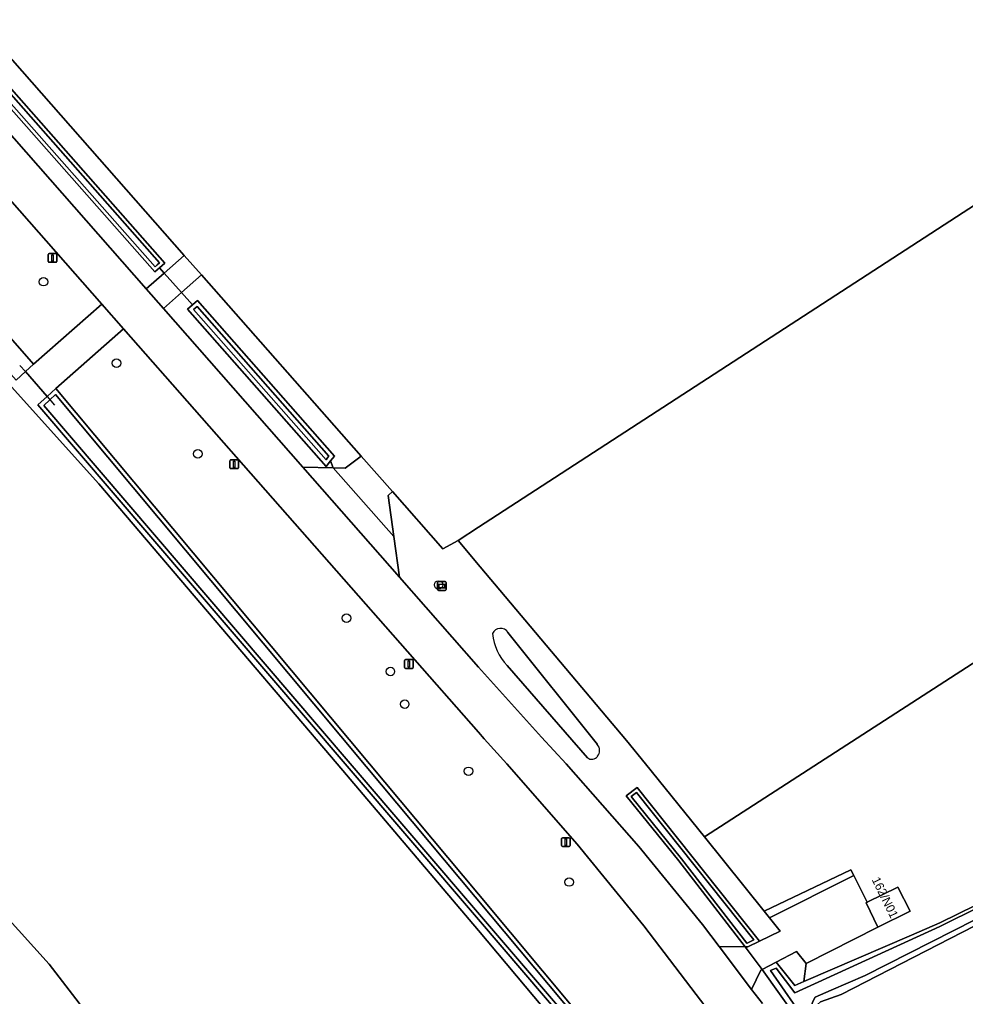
# Model space of a CAD drawing. Extents: x 156061 to 157804, y 383437 to 385640.
# Drawn here: x 157447.3 to 157555.9, y 383973.3 to 384085.5 of the extents above; entities that cross this region are included whole.
import ezdxf

# ---------------------------------------------------------------- set-up
doc = ezdxf.new("R2010")
doc.units = 0
for name, color, linetype in [('IMGEO_Berm_groen', 7, 'Continuous'), ('IMGEO_Boom', 7, 'Continuous'), ('IMGEO_Duiker', 7, 'Continuous'), ('IMGEO_Grasland_overig', 7, 'Continuous'), ('IMGEO_Groenvoorziening', 7, 'Continuous'), ('IMGEO_Haag', 7, 'Continuous'), ('IMGEO_Hek', 7, 'Continuous'), ('IMGEO_Lichtmast', 7, 'Continuous'), ('IMGEO_Naaldbos', 7, 'Continuous'), ('IMGEO_Oever', 7, 'Continuous'), ('IMGEO_Pand', 7, 'Continuous'), ('IMGEO_Pand_nummerreeks', 7, 'Continuous'), ('IMGEO_Rijbaan_lokaal_gesloten', 7, 'Continuous'), ('IMGEO_Rijbaan_lokaal_open', 7, 'Continuous'), ('IMGEO_Verklikker', 7, 'Continuous'), ('IMGEO_Waterloop', 7, 'Continuous')]:
    doc.layers.add(name, color=color, linetype=linetype)

msp = doc.modelspace()

# ---------------------------------------------------------------- linework, layer by layer
at = {"layer": 'IMGEO_Berm_groen'}
for points in [[(157340.41, 384192.86), (157351.29, 384180.48), (157461.84, 384054.56), (157463.91, 384056.38), (157463.38, 384056.98), (157462.83, 384056.5), (157343.68, 384191.47)], [(157318.6, 384190.2), (157317.96, 384189.64), (157344.19, 384159.18), (157364.55, 384136), (157393.61, 384102.92), (157399.11, 384096.66), (157446.05, 384043.69), (157456.41, 384032.18), (157483.79, 384000), (157500, 383980.87), (157519.27, 383957.9), (157520.38, 383958.3), (157500, 383982.12), (157484.69, 384000), (157449.42, 384041.22), (157450.46, 384042.19), (157447.97, 384045.05), (157446.91, 384044.08), (157389.32, 384108.91), (157390.82, 384110.23), (157391.84, 384111.13), (157448.89, 384045.9), (157456.76, 384052.82), (157342.96, 384182.28)], [(157527.33, 383970.45), (157519, 383981.4), (157511.33, 383990.78), (157503.27, 384000), (157500.68, 384002.86), (157500, 384003.63), (157459.26, 384049.98), (157451.47, 384043.13), (157487.5, 384000), (157500, 383985.04), (157521.88, 383958.85)], [(157503.4, 384015.1), (157513.66, 384002.23)], [(157512.54, 384000.71), (157503.29, 384011.29)]]:
    msp.add_lwpolyline(points, dxfattribs=at)
for points in [[(157463.91, 384056.38), (157461.84, 384054.56), (157463.82, 384052.3), (157465.9, 384054.13)], [(157466.6, 384052.22), (157467.16, 384052.71), (157465.9, 384054.13), (157463.82, 384052.3), (157479.83, 384034.07), (157483.33, 384033.99), (157483.03, 384034.79), (157482.52, 384034.17)], [(157483.33, 384033.99), (157479.83, 384034.07), (157490.93, 384021.43), (157490.28, 384026.1)], [(157500.2, 384022.65), (157497.66, 384025.67), (157495.9, 384024.71), (157490.12, 384031.28), (157489.62, 384030.82), (157490.28, 384026.1), (157490.93, 384021.43), (157500, 384011.09), (157507.25, 384003.05), (157510.09, 384000), (157518.43, 383990.52), (157525.74, 383981.55), (157527.64, 383979.04), (157530.64, 383978.98), (157523.02, 383988.86), (157516.98, 383996.33), (157518.23, 383997.3), (157532.29, 383979.64), (157534.64, 383980.79), (157533.45, 383982.31), (157532.83, 383983.08), (157525.95, 383991.61), (157519.18, 384000), (157517.01, 384002.7)]]:
    msp.add_lwpolyline(points, close=True, dxfattribs=at)
for centre, radius, start, end in [((157502.55, 384014.57), 1, 31.6822, 156.9523), ((157507.72, 384015.51), 6.11, 185.0653, 223.6347), ((157512.91, 384001.54), 1.01, 318.1974, 42.3929), ((157513.03, 384001.28), 0.758, 229.1685, 326.9357)]:
    msp.add_arc(centre, radius, start, end, dxfattribs=at)
at = {"layer": 'IMGEO_Boom'}
for centre in [(157450.06, 384055.38), (157458.43, 384046.03), (157467.78, 384035.61), (157495.43, 384020.55), (157484.85, 384016.73), (157489.89, 384010.6), (157491.54, 384006.85), (157498.86, 383999.15), (157510.42, 383986.43)]:
    msp.add_circle(centre, 0.489, dxfattribs=at)
at = {"layer": 'IMGEO_Duiker'}
msp.add_lwpolyline([(157447.34, 384045.77), (157447.97, 384045.05), (157450.46, 384042.19), (157451.33, 384041.19)], dxfattribs=at)
at = {"layer": 'IMGEO_Grasland_overig'}
for points in [[(157468.2, 384056.16), (157466.22, 384058.41), (157463.91, 384056.38), (157465.9, 384054.13)], [(157451.47, 384043.13), (157459.26, 384049.98), (157456.76, 384052.82), (157448.89, 384045.9), (157447.97, 384045.05), (157450.46, 384042.19)], [(157489.62, 384030.82), (157490.12, 384031.28), (157486.53, 384035.35), (157484.7, 384033.96), (157483.33, 384033.99), (157490.28, 384026.1)]]:
    msp.add_lwpolyline(points, close=True, dxfattribs=at)
at = {"layer": 'IMGEO_Groenvoorziening'}
for points in [[(157375.38, 384222.59), (157376.59, 384220.76), (157342.51, 384199.14), (157412.58, 384119.43), (157466.22, 384058.41), (157468.2, 384056.16), (157486.53, 384035.35), (157490.12, 384031.28), (157495.9, 384024.71), (157497.66, 384025.67), (157500, 384027.19), (157642, 384119.41), (157643.26, 384117.4), (157752.8, 384188.65), (157752.54, 384194.33), (157751.65, 384205.4), (157750.08, 384220.37), (157749.32, 384226.2), (157748.06, 384232.65), (157745.14, 384247.49), (157743.64, 384254.59), (157738.42, 384274.55), (157728.47, 384313.42)], [(157340.2, 384197.97), (157344.9, 384192.66), (157463.98, 384057.5), (157463.38, 384056.98), (157463.91, 384056.38), (157466.22, 384058.41), (157412.58, 384119.43), (157342.51, 384199.14), (157376.59, 384220.76), (157375.38, 384222.59), (157343.39, 384202.41)], [(157642, 384119.41), (157500, 384027.19), (157497.66, 384025.67), (157500.2, 384022.65), (157517.01, 384002.7), (157519.18, 384000), (157525.95, 383991.61), (157642.66, 384067.03), (157664.05, 384080.85), (157668.86, 384071.41), (157701.95, 384072.77), (157719.58, 384083.63), (157721.28, 384082.41), (157730.2, 384064.28), (157731.75, 384064.23), (157756.47, 384074.37), (157756.55, 384074.87), (157757.36, 384079.82), (157760.48, 384099.13)], [(157319.02, 384000), (157343.68, 383972.81), (157358.66, 383956.01), (157373.77, 383939.34), (157386.41, 383926.07), (157399.25, 383913.04), (157423.1, 383919.46), (157447.61, 383928.82), (157500, 383950.08), (157519.27, 383957.9), (157500, 383980.87), (157483.79, 384000), (157456.41, 384032.18), (157446.05, 384043.69), (157399.11, 384096.66)], [(157683.71, 383998.2), (157679.87, 383996.94), (157678.86, 384000), (157676.51, 384007.11), (157673.93, 384007.49), (157671.91, 384009.46), (157668.41, 384017.54), (157659.62, 384031.98), (157656.19, 384033.53), (157656.8, 384032.66), (157593.24, 384000), (157541.68, 383973.51), (157539.29, 383972.68), (157538.96, 383972.37), (157554.47, 383951.89), (157556.32, 383951.02)], [(157427.78, 384002.36), (157450.71, 383977), (157457.73, 383967.9)], [(157542, 383963.16), (157538.56, 383967.99), (157532.58, 383976.37), (157532.42, 383976.29), (157531.38, 383974.1), (157532.61, 383972.47)]]:
    msp.add_lwpolyline(points, dxfattribs=at)
for points in [[(157656.19, 384033.53), (157659.62, 384031.98), (157642.66, 384067.03), (157525.95, 383991.61), (157532.83, 383983.08), (157542.78, 383987.84), (157543.11, 383987.19), (157544.65, 383984.1), (157548.18, 383985.84), (157549.57, 383983.08), (157545.89, 383981.26), (157537.64, 383977.09), (157537.39, 383975.02), (157549.75, 383980.34), (157553.01, 383981.76), (157590.21, 384000)], [(157467.16, 384052.71), (157467.74, 384053.23), (157483.49, 384035.34), (157483.03, 384034.79), (157483.33, 384033.99), (157484.7, 384033.96), (157486.53, 384035.35), (157468.2, 384056.16), (157465.9, 384054.13)], [(157533.45, 383982.31), (157543.11, 383987.19), (157542.78, 383987.84), (157532.83, 383983.08)], [(157537.39, 383975.02), (157537.64, 383977.09), (157536.53, 383978.45), (157534.2, 383977.23), (157536.33, 383974.56)]]:
    msp.add_lwpolyline(points, close=True, dxfattribs=at)
at = {"layer": 'IMGEO_Haag'}
msp.add_lwpolyline([(157533.45, 383982.31), (157543.11, 383987.19), (157542.78, 383987.84), (157532.83, 383983.08)], close=True, dxfattribs=at)
at = {"layer": 'IMGEO_Hek'}
for points in [[(157376.59, 384220.76), (157342.51, 384199.14), (157412.58, 384119.43), (157466.22, 384058.41)], [(157500, 384027.19), (157642, 384119.41)], [(157466.22, 384058.41), (157468.2, 384056.16)], [(157468.2, 384056.16), (157486.53, 384035.35)], [(157486.53, 384035.35), (157490.12, 384031.28)], [(157490.12, 384031.28), (157495.9, 384024.71)], [(157497.66, 384025.67), (157500, 384027.19)], [(157495.9, 384024.71), (157497.66, 384025.67)], [(157500.2, 384022.65), (157497.66, 384025.67)], [(157519.18, 384000), (157517.01, 384002.7), (157500.2, 384022.65)], [(157525.95, 383991.61), (157519.18, 384000)], [(157532.83, 383983.08), (157525.95, 383991.61)], [(157543.11, 383987.19), (157542.78, 383987.84), (157532.83, 383983.08)], [(157544.65, 383984.1), (157543.11, 383987.19)], [(157545.89, 383981.26), (157537.64, 383977.09)]]:
    msp.add_lwpolyline(points, dxfattribs=at)
at = {"layer": 'IMGEO_Lichtmast'}
for p, q in [((157450.59, 384057.71), (157450.59, 384058.51)), ((157450.59, 384058.51), (157450.59, 384057.71)), ((157450.69, 384058.61), (157451.48, 384058.61)), ((157451.48, 384058.61), (157450.69, 384058.61)), ((157451.58, 384058.51), (157451.58, 384057.71)), ((157451.58, 384057.71), (157451.58, 384058.51)), ((157451.48, 384057.61), (157450.69, 384057.61)), ((157450.69, 384057.61), (157451.48, 384057.61)), ((157471.45, 384034.01), (157471.45, 384034.81)), ((157471.45, 384034.81), (157471.45, 384034.01)), ((157471.55, 384034.91), (157472.34, 384034.91)), ((157472.34, 384034.91), (157471.55, 384034.91)), ((157472.44, 384034.81), (157472.44, 384034.01)), ((157472.44, 384034.01), (157472.44, 384034.81)), ((157472.34, 384033.91), (157471.55, 384033.91)), ((157471.55, 384033.91), (157472.34, 384033.91)), ((157491.53, 384011.07), (157491.53, 384011.87)), ((157491.53, 384011.87), (157491.53, 384011.07)), ((157491.63, 384011.97), (157492.42, 384011.97)), ((157492.42, 384011.97), (157491.63, 384011.97)), ((157492.52, 384011.87), (157492.52, 384011.07)), ((157492.52, 384011.07), (157492.52, 384011.87)), ((157492.42, 384010.97), (157491.63, 384010.97)), ((157491.63, 384010.97), (157492.42, 384010.97)), ((157509.55, 383990.61), (157509.55, 383991.41)), ((157509.55, 383991.41), (157509.55, 383990.61)), ((157509.65, 383991.51), (157510.44, 383991.51)), ((157510.44, 383991.51), (157509.65, 383991.51)), ((157510.54, 383991.41), (157510.54, 383990.61)), ((157510.54, 383990.61), (157510.54, 383991.41)), ((157510.44, 383990.51), (157509.65, 383990.51)), ((157509.65, 383990.51), (157510.44, 383990.51))]:
    msp.add_line(p, q, dxfattribs=at)
for points in [[(157451.01, 384058.48), (157451.16, 384058.48), (157451.16, 384057.73), (157451.01, 384057.73), (157451.01, 384058.48)], [(157471.87, 384034.78), (157472.02, 384034.78), (157472.02, 384034.03), (157471.87, 384034.03), (157471.87, 384034.78)], [(157491.95, 384011.85), (157492.1, 384011.85), (157492.1, 384011.1), (157491.95, 384011.1), (157491.95, 384011.85)], [(157509.97, 383991.38), (157510.12, 383991.38), (157510.12, 383990.63), (157509.97, 383990.63), (157509.97, 383991.38)]]:
    msp.add_lwpolyline(points, dxfattribs=at)
for centre, start, end in [((157450.69, 384058.51), 90, 180), ((157450.69, 384058.51), 90, 180), ((157451.48, 384058.51), 0, 90), ((157451.48, 384058.51), 360, 90), ((157450.69, 384057.71), 180, 270), ((157450.69, 384057.71), 180, 270), ((157451.48, 384057.71), 270, 0), ((157451.48, 384057.71), 270, 0), ((157471.55, 384034.81), 90, 180), ((157471.55, 384034.81), 90, 180), ((157472.34, 384034.81), 0, 90), ((157472.34, 384034.81), 360, 90), ((157471.55, 384034.01), 180, 270), ((157471.55, 384034.01), 180, 270), ((157472.34, 384034.01), 270, 0), ((157472.34, 384034.01), 270, 0), ((157491.63, 384011.87), 90, 180), ((157491.63, 384011.87), 90, 180), ((157492.42, 384011.87), 0, 90), ((157492.42, 384011.87), 360, 90), ((157491.63, 384011.07), 180, 270), ((157491.63, 384011.07), 180, 270), ((157492.42, 384011.07), 270, 0), ((157492.42, 384011.07), 270, 0), ((157509.65, 383991.41), 90, 180), ((157509.65, 383991.41), 90, 180), ((157510.44, 383991.41), 0, 90), ((157510.44, 383991.41), 360, 90), ((157509.65, 383990.61), 180, 270), ((157509.65, 383990.61), 180, 270), ((157510.44, 383990.61), 270, 0), ((157510.44, 383990.61), 270, 0)]:
    msp.add_arc(centre, 0.1, start, end, dxfattribs=at)
at = {"layer": 'IMGEO_Naaldbos'}
msp.add_lwpolyline([(157427.78, 384002.36), (157428.16, 383997.33), (157425.96, 383992.38), (157421.54, 383990.17), (157416.03, 383990.5), (157424.72, 383980.52), (157429.47, 383965.92), (157425.19, 383960), (157425.98, 383955.9), (157432.13, 383957.26), (157438.21, 383958.78), (157446.36, 383961.6), (157453.38, 383965.1), (157457.73, 383967.9), (157450.71, 383977)], close=True, dxfattribs=at)
at = {"layer": 'IMGEO_Oever'}
for points in [[(157343.68, 384191.47), (157462.83, 384056.5), (157463.38, 384056.98), (157463.98, 384057.5), (157344.9, 384192.66)], [(157344.59, 384192.37), (157463.38, 384057.54), (157463.1, 384057.3), (157462.87, 384057.1), (157385.2, 384145.03), (157343.99, 384191.76)], [(157500, 383985.04), (157487.5, 384000), (157451.47, 384043.13), (157450.46, 384042.19), (157449.42, 384041.22), (157484.69, 384000), (157500, 383982.12), (157520.38, 383958.3), (157521.18, 383957.37), (157500, 383948.87), (157447.92, 383927.96)], [(157520.75, 383958.62), (157500.37, 383982.43), (157485.06, 384000.31), (157450.08, 384041.18), (157450.78, 384041.83), (157451.42, 384042.43), (157487.13, 383999.69), (157499.63, 383984.73), (157521.74, 383958.27)], [(157538.96, 383972.37), (157539.29, 383972.68), (157541.68, 383973.51), (157593.24, 384000), (157656.8, 384032.66), (157656.19, 384033.53), (157590.21, 384000), (157553.01, 383981.76), (157549.75, 383980.34), (157537.39, 383975.02), (157536.33, 383974.56), (157534.2, 383977.23), (157532.58, 383976.37), (157538.56, 383967.99), (157542, 383963.16)], [(157563.7, 383930.34), (157553.42, 383947.27), (157549.77, 383953.21), (157537.79, 383970.15), (157533.55, 383976.27), (157534.18, 383976.52), (157536.35, 383973.72), (157553, 383981.32), (157590.9, 384000.13)], [(157448.61, 383926.22), (157451.61, 383927.43), (157473.7, 383936.38), (157500, 383947.02), (157516, 383953.5), (157523.94, 383956.8), (157529.6, 383959.15), (157531.35, 383957.26), (157531.69, 383956.9), (157532.22, 383957.33), (157532.95, 383957.92), (157532.92, 383958.91), (157530.15, 383962.42), (157521.88, 383958.85), (157500, 383985.04)], [(157559.58, 383983.38), (157544.42, 383975.69), (157540.51, 383974.02), (157538.66, 383973.21), (157538.39, 383972.7), (157538.13, 383971.94), (157538.33, 383971.09), (157545.65, 383961.38), (157551.34, 383953.49), (157553.33, 383951.7), (157563.27, 383945.93)]]:
    msp.add_lwpolyline(points, dxfattribs=at)
for points in [[(157391.84, 384111.13), (157390.82, 384110.23), (157389.32, 384108.91), (157446.91, 384044.08), (157447.97, 384045.05), (157448.89, 384045.9)], [(157467.74, 384053.23), (157467.16, 384052.71), (157466.6, 384052.22), (157482.52, 384034.17), (157483.03, 384034.79), (157483.49, 384035.34)], [(157467.7, 384052.53), (157482.84, 384035.33), (157482.65, 384035.1), (157482.51, 384034.93), (157467.3, 384052.18), (157467.48, 384052.34)], [(157518.23, 383997.3), (157516.98, 383996.33), (157523.02, 383988.86), (157530.64, 383978.98), (157530.94, 383978.98), (157532.29, 383979.64)], [(157518.16, 383996.73), (157531.65, 383979.78), (157530.85, 383979.39), (157530.84, 383979.39), (157523.34, 383989.11), (157517.56, 383996.26)]]:
    msp.add_lwpolyline(points, close=True, dxfattribs=at)
at = {"layer": 'IMGEO_Pand'}
msp.add_lwpolyline([(157544.65, 383984.1), (157544.52, 383984.04), (157545.89, 383981.26), (157549.57, 383983.08), (157548.18, 383985.84)], close=True, dxfattribs=at)
at = {"layer": 'IMGEO_Rijbaan_lokaal_gesloten'}
for points in [[(157342.96, 384182.28), (157456.76, 384052.82), (157459.26, 384049.98), (157500, 384003.63), (157500.68, 384002.86), (157503.27, 384000), (157511.33, 383990.78), (157519, 383981.4), (157527.33, 383970.45), (157530.5, 383965.93), (157530.89, 383965.44), (157535.32, 383959.69), (157540.42, 383951.06), (157542.83, 383947.51), (157548.36, 383938.61), (157552.88, 383931.4), (157563.85, 383910.77)], [(157461.84, 384054.56), (157351.29, 384180.48)], [(157532.61, 383972.47), (157531.38, 383974.1), (157527.64, 383979.04), (157525.74, 383981.55), (157518.43, 383990.52), (157510.09, 384000), (157507.25, 384003.05), (157500, 384011.09), (157490.93, 384021.43), (157479.83, 384034.07), (157463.82, 384052.3), (157461.84, 384054.56)]]:
    msp.add_lwpolyline(points, dxfattribs=at)
at = {"layer": 'IMGEO_Rijbaan_lokaal_open'}
for points in [[(157532.58, 383976.37), (157534.2, 383977.23), (157536.53, 383978.45), (157537.64, 383977.09), (157545.89, 383981.26), (157544.52, 383984.04), (157544.65, 383984.1), (157543.11, 383987.19), (157533.45, 383982.31), (157534.64, 383980.79), (157532.29, 383979.64), (157530.94, 383978.98), (157530.64, 383978.98)], [(157532.58, 383976.37), (157530.64, 383978.98), (157527.64, 383979.04), (157531.38, 383974.1), (157532.42, 383976.29)]]:
    msp.add_lwpolyline(points, close=True, dxfattribs=at)
at = {"layer": 'IMGEO_Verklikker'}
for p, q in [((157495.3, 384020.03), (157495.3, 384020.83)), ((157495.3, 384020.83), (157495.3, 384020.03)), ((157495.4, 384020.93), (157496.19, 384020.93)), ((157496.19, 384020.93), (157495.4, 384020.93)), ((157496.29, 384020.83), (157496.29, 384020.03)), ((157496.29, 384020.03), (157496.29, 384020.83)), ((157496.19, 384019.93), (157495.4, 384019.93)), ((157495.4, 384019.93), (157496.19, 384019.93))]:
    msp.add_line(p, q, dxfattribs=at)
for points in [[(157495.4, 384020.66), (157496.19, 384020.66), (157496.19, 384020.19), (157495.4, 384020.19), (157495.4, 384020.66)], [(157495.47, 384020.59), (157495.47, 384020.26), (157496.13, 384020.26), (157496.13, 384020.59), (157495.47, 384020.59)]]:
    msp.add_lwpolyline(points, dxfattribs=at)
for centre, start, end in [((157495.4, 384020.83), 90, 180), ((157495.4, 384020.83), 90, 180), ((157496.19, 384020.83), 0, 90), ((157496.19, 384020.83), 360, 90), ((157495.4, 384020.03), 180, 270), ((157495.4, 384020.03), 180, 270), ((157496.19, 384020.03), 270, 0), ((157496.19, 384020.03), 270, 0)]:
    msp.add_arc(centre, 0.1, start, end, dxfattribs=at)
at = {"layer": 'IMGEO_Waterloop'}
for points in [[(157343.99, 384191.76), (157385.2, 384145.03), (157462.87, 384057.1), (157463.1, 384057.3), (157463.38, 384057.54), (157344.59, 384192.37)], [(157521.74, 383958.27), (157499.63, 383984.73), (157487.13, 383999.69), (157451.42, 384042.43), (157450.78, 384041.83), (157450.08, 384041.18), (157485.06, 384000.31), (157500.37, 383982.43), (157520.75, 383958.62)], [(157513.66, 384002.23), (157503.4, 384015.1)], [(157503.29, 384011.29), (157512.54, 384000.71)], [(157590.9, 384000.13), (157553, 383981.32), (157536.35, 383973.72), (157534.18, 383976.52), (157533.55, 383976.27), (157537.79, 383970.15), (157549.77, 383953.21), (157553.42, 383947.27), (157563.7, 383930.34)], [(157563.27, 383945.93), (157553.33, 383951.7), (157551.34, 383953.49), (157545.65, 383961.38), (157538.33, 383971.09), (157538.13, 383971.94), (157538.39, 383972.7), (157538.66, 383973.21), (157540.51, 383974.02), (157544.42, 383975.69), (157559.58, 383983.38)]]:
    msp.add_lwpolyline(points, dxfattribs=at)
for points in [[(157467.7, 384052.53), (157467.48, 384052.34), (157467.3, 384052.18), (157482.51, 384034.93), (157482.65, 384035.1), (157482.84, 384035.33)], [(157518.16, 383996.73), (157517.56, 383996.26), (157523.34, 383989.11), (157530.84, 383979.39), (157530.85, 383979.39), (157531.65, 383979.78)]]:
    msp.add_lwpolyline(points, close=True, dxfattribs=at)
for centre, radius, start, end in [((157502.55, 384014.57), 1, 31.6822, 156.9523), ((157507.72, 384015.51), 6.11, 185.0653, 223.6347), ((157512.91, 384001.54), 1.01, 318.1974, 42.3929), ((157513.03, 384001.28), 0.758, 229.1685, 326.9357)]:
    msp.add_arc(centre, radius, start, end, dxfattribs=at)

# ---------------------------------------------------------------- texts
at = {"layer": 'IMGEO_Pand_nummerreeks'}
msp.add_text('162/N01', height=1, rotation=296.0935, dxfattribs=at).set_placement((157545.14, 383986.71))

doc.saveas('drawing.dxf')
